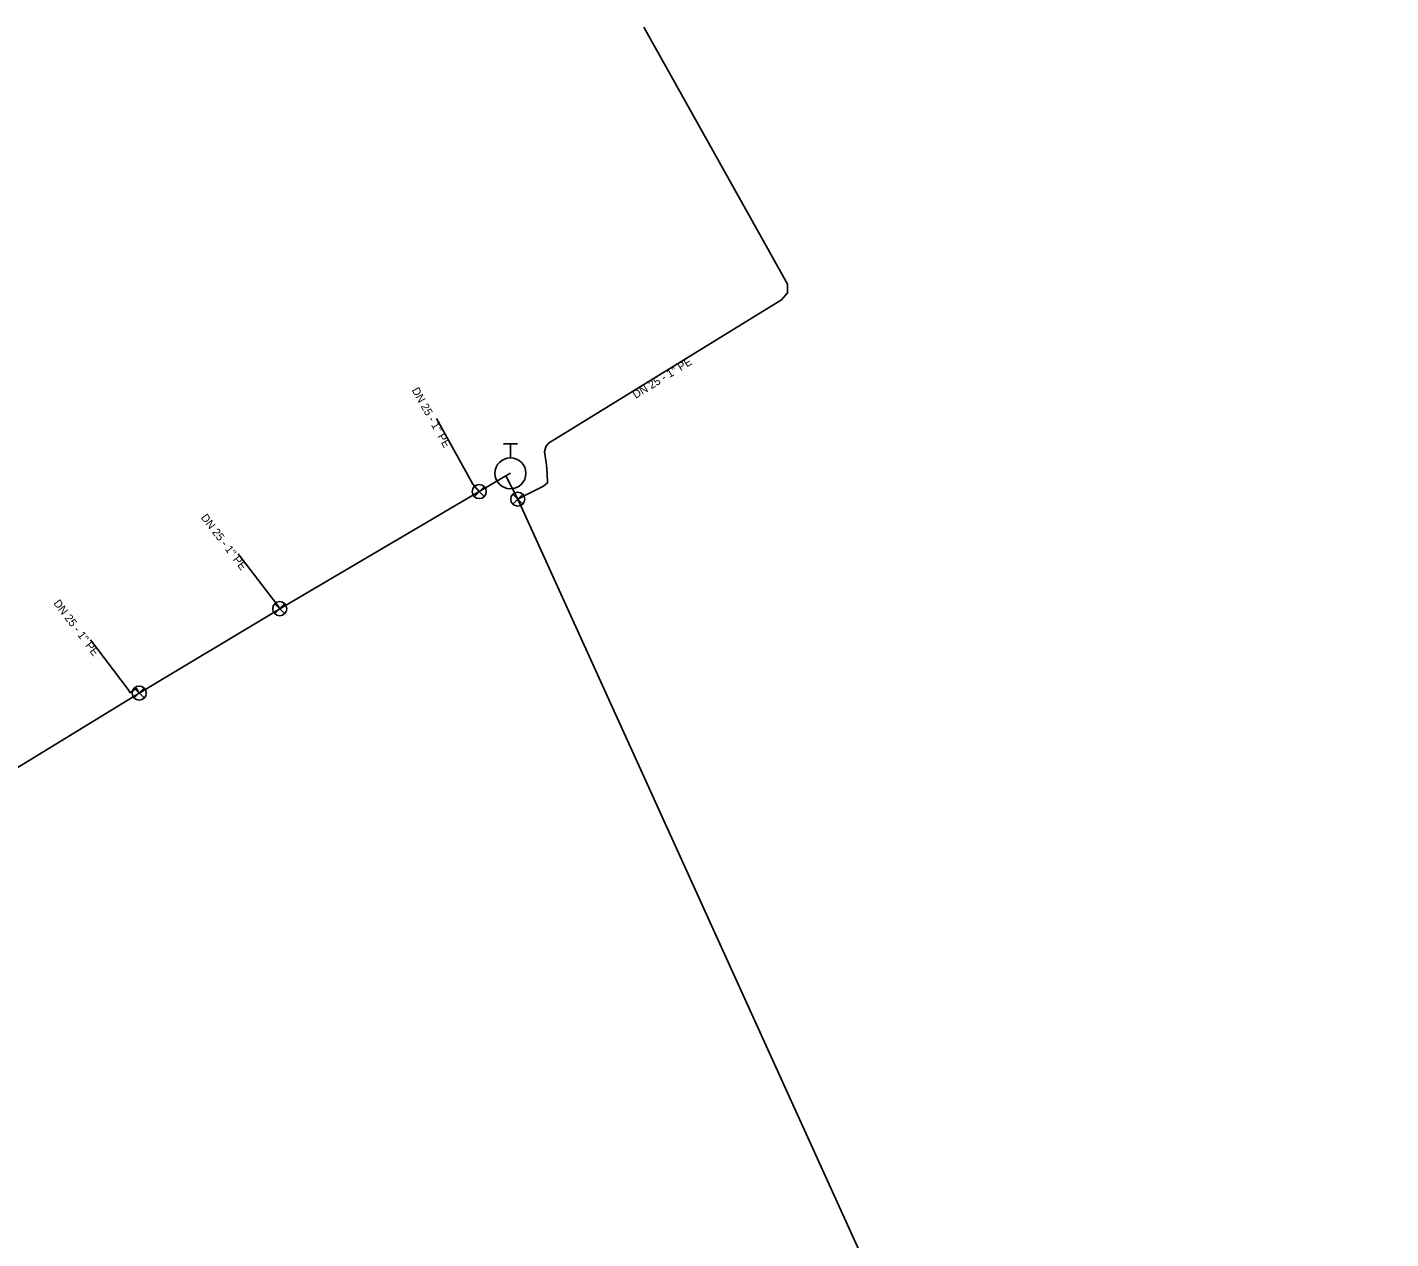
# Model space of a CAD drawing. Extents: x -492321 to -492053, y -1126159 to -1125902.
# Drawn here: x -492248.3 to -492170.8, y -1126090.5 to -1126021.6 of the extents above; entities that cross this region are included whole.
import ezdxf

# ---------------------------------------------------------------- set-up
doc = ezdxf.new("R2010")
doc.units = 0
for name, color, linetype in [('_hydrantova_odbocka_', 7, 'Continuous'), ('_pripojka_prevzato_z_dokumentace_', 7, 'Continuous'), ('_pripojka_priblizne_', 7, 'Continuous'), ('_voda_smvak_prevzato_z_dokumentace_', 7, 'Continuous'), ('Default', 7, 'Continuous'), ('MoLevel 28', 7, 'Continuous'), ('MoLevel 32', 7, 'Continuous'), ('MoLevel 53', 7, 'Continuous')]:
    doc.layers.add(name, color=color, linetype=linetype)

# ---------------------------------------------------------------- blocks, each defined once
blk = doc.blocks.new('_uzaver_pripojka_')
at = {"layer": 'Default'}
for p, q in [((-0.000035, -0.000035), (0.000035, 0.000035)), ((0.000035, -0.000035), (-0.000035, 0.000035))]:
    blk.add_line(p, q, dxfattribs=at)
for radius in [0.00005, 0.0000025]:
    blk.add_circle((0, 0), radius, dxfattribs=at)
blk = doc.blocks.new('_hydrant_voda_')
at = {"layer": 'Default'}
for p, q in [((-0.0000225, 0.000095), (0.0000225, 0.000095)), ((0, 0.000095), (0, 0.00005))]:
    blk.add_line(p, q, dxfattribs=at)
blk.add_circle((0, 0), 0.00005, dxfattribs=at)

msp = doc.modelspace()

# ---------------------------------------------------------------- linework, layer by layer
at = {"layer": '_hydrantova_odbocka_'}
msp.add_line((-492221.11, -1126047.14), (-492220.85, -1126046.99), dxfattribs=at)
at = {"layer": '_pripojka_prevzato_z_dokumentace_'}
for p, q in [((-492222.62, -1126048.03), (-492222.98, -1126047.61)), ((-492220.43, -1126048.46), (-492219.83, -1126048.15)), ((-492233.97, -1126054.69), (-492234.1, -1126054.49))]:
    msp.add_line(p, q, dxfattribs=at)
msp.add_lwpolyline([(-492241.96, -1126059.49), (-492242.13, -1126059.22), (-492242.48, -1126059.48)], dxfattribs=at)
at = {"layer": '_pripojka_priblizne_'}
for p, q in [((-492206.209, -1126034.224), (-492213.263, -1126021.618)), ((-492222.98, -1126047.61), (-492225.06, -1126043.88)), ((-492234.1, -1126054.49), (-492236.336, -1126051.568))]:
    msp.add_line(p, q, dxfattribs=at)
for points in [[(-492219.83, -1126048.15), (-492218.96, -1126047.713), (-492218.73, -1126047.54), (-492218.761, -1126047.009), (-492218.793, -1126046.508), (-492218.919, -1126045.764), (-492218.832, -1126045.486), (-492218.679, -1126045.276), (-492205.439, -1126037.129), (-492205.088, -1126036.728), (-492205.088, -1126036.227), (-492206.209, -1126034.224)], [(-492242.48, -1126059.48), (-492242.59, -1126059.29), (-492244.728, -1126056.455)]]:
    msp.add_lwpolyline(points, dxfattribs=at)
at = {"layer": '_voda_smvak_prevzato_z_dokumentace_'}
msp.add_lwpolyline([(-492320.55, -1126109.337), (-492314.27, -1126105.27), (-492304.68, -1126098.93), (-492293.08, -1126091.26), (-492282.11, -1126084.21), (-492270.76, -1126077.22), (-492264.09, -1126073.17), (-492253.41, -1126066.5), (-492241.96, -1126059.49), (-492233.97, -1126054.69), (-492222.62, -1126048.03), (-492221.11, -1126047.14), (-492220.43, -1126048.46), (-492198.94, -1126095.74), (-492189.88, -1126116.75), (-492173.99, -1126152.32), (-492170.782, -1126159.439)], dxfattribs=at)

# ---------------------------------------------------------------- block references
at = {"layer": 'MoLevel 28', "xscale": 17636.68430335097, "yscale": 17636.68430335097}
msp.add_blockref('_hydrant_voda_', (-492220.85, -1126046.99), dxfattribs=at)
at = {"layer": 'MoLevel 53', "xscale": 7999.999999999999, "yscale": 7999.999999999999}
for p in [(-492222.62, -1126048.03), (-492220.43, -1126048.46), (-492233.97, -1126054.69), (-492241.96, -1126059.49)]:
    msp.add_blockref('_uzaver_pripojka_', p, dxfattribs=at)

# ---------------------------------------------------------------- texts
at = {"layer": 'MoLevel 32'}
for rotation, p in [(31.60533, (-492213.723, -1126042.761)), (299.14582, (-492226.474, -1126042.256)), (307.42428, (-492238.481, -1126049.513)), (307.02158, (-492246.859, -1126054.385))]:
    msp.add_text("DN 25 - 1'' PE", height=0.455, rotation=rotation, dxfattribs=at).set_placement(p)

doc.saveas('drawing.dxf')
